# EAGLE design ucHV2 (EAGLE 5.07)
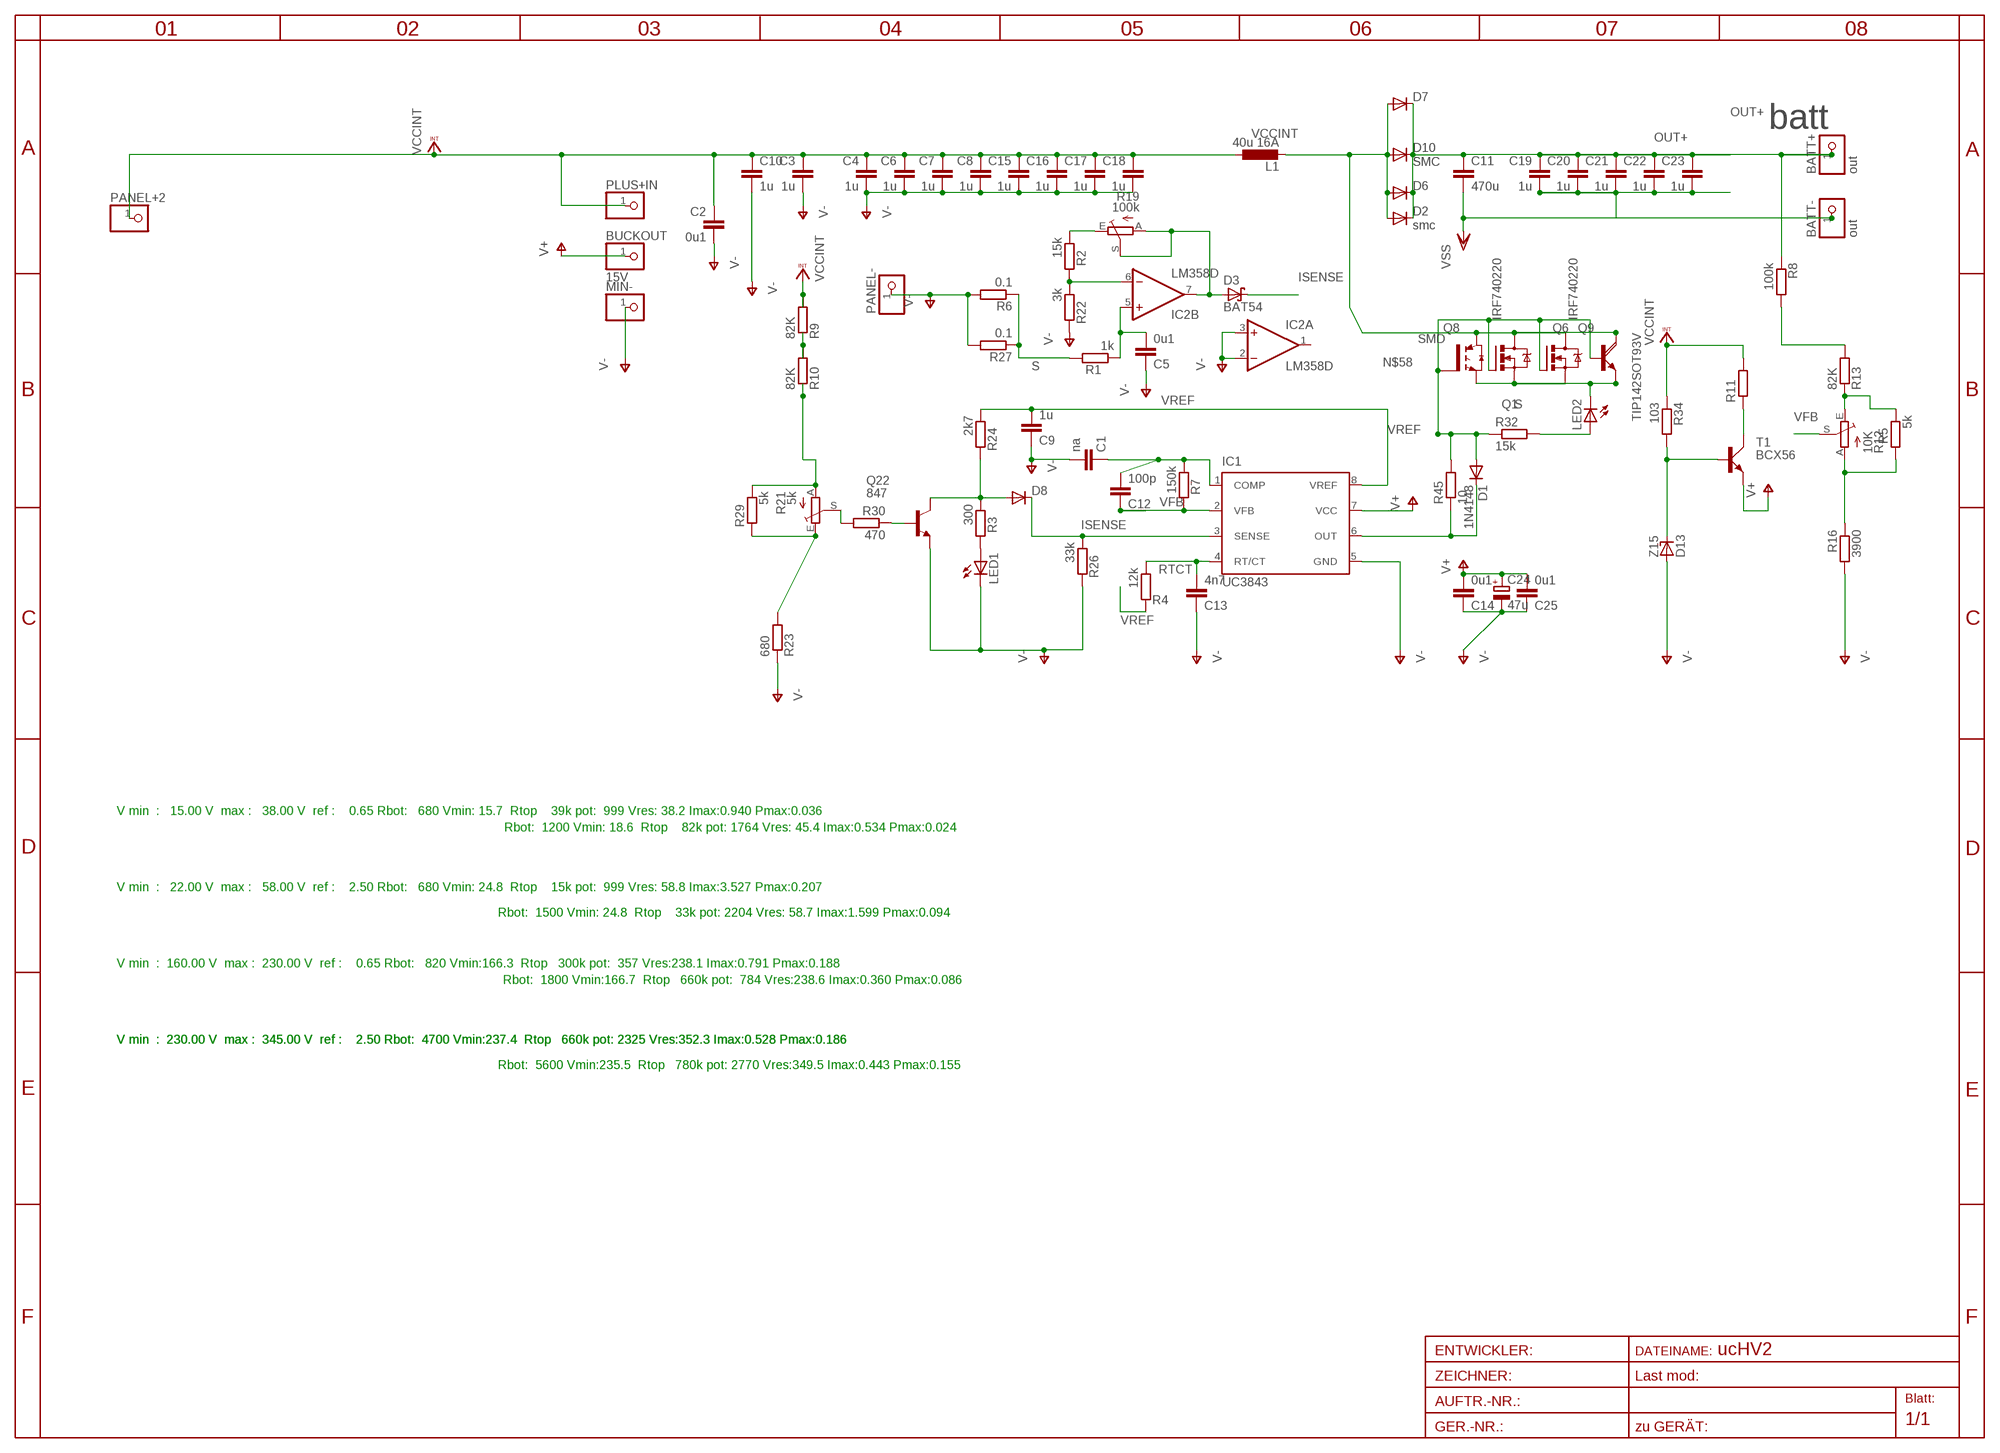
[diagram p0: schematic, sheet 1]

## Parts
BATT+  out  PINHD-1X11MM6  [1X1MM8]
BATT-  out  PINHD-1X11MM6  [1X1MM8]
BUCKOUT  15V  PINHD-1X11MM0  [1X1MM0]
C1  na  C-EUC0805  [C0805]
C2  0u1  C-EUC1206  [C1206]
C3  1u  C-EUC1206  [C1206]
C4  1u  C-EUC1206  [C1206]
C5  0u1  C-EUC0805  [C0805]
C6  1u  C-EUC1206  [C1206]
C7  1u  C-EUC1206  [C1206]
C8  1u  C-EUC1206  [C1206]
C9  1u  C-EUC1206  [C1206]
C10  1u  C-EU075-052X106  [C075-052X106]
C11  470u  C-EU075-052X106  [C075-052X106]
C12  100p  C-EUC0805  [C0805]
C13  4n7  C-EUC0805  [C0805]
C14  0u1  C-EUC3216  [C3216]
C15  1u  C-EUC1206  [C1206]
C16  1u  C-EUC1206  [C1206]
C17  1u  C-EUC1206  [C1206]
C18  1u  C-EUC1206  [C1206]
C19  1u  C-EUC1206  [C1206]
C20  1u  C-EUC1206  [C1206]
C21  1u  C-EUC1206  [C1206]
C22  1u  C-EUC1206  [C1206]
C23  1u  C-EUC1206  [C1206]
C24  47u  CPOL-EUSMCA  [SMC_A]
C25  0u1  C-EUC1206  [C1206]
D1  1N4148  DIODE-MINIMELF  [MINIMELF]
D2  smc  DIODE-SMC  [SMC]
D3  BAT54  [SOT23]
D6  DIODE-SMC  [SMC]
D7  DIODE-SMC  [SMC]
D8  DIODE-MINIMELF  [MINIMELF]
D10  SMC  DIODE-SMC  [SMC]
D13  Z15  ZENER-DIODESOD80C  [SOD80C]
IC1  UC3843  UC1843D8  [SO-08]
IC2  LM358D  [SO08]
L1  40u 16A  L-EU  [RING]
LED1  LEDCHIPLED_1206  [CHIPLED_1206]
LED2  LEDCHIPLED_1206  [CHIPLED_1206]
MIN-  PINHD-1X11MM0  [1X1MM0]
PANEL+2  PINHD-1X11MM6  [1X1MM8]
PANEL-  PINHD-1X11MM6  [1X1MM8]
PLUS+IN  PINHD-1X11MM0  [1X1MM0]
Q1  IRF740220  [TO220BV]
Q6  IRF740220  [TO220BV]
Q8  SMD  IRG4BC15UD-S  [D2PACK]
Q9  TIP142SOT93V  [SOT93V]
Q22  847  BC847ASMD  [SOT23]
R1  1k  R-EU_R0805  [R0805]
R2  15k  R-EU_R0805  [R0805]
R3  300  R-EU_R0805  [R0805]
R4  12k  R-EU_R0805  [R0805]
R5  5k  R-EU_R0805  [R0805]
R6  0.1  R-EU_0207/10  [0207/10]
R7  150k  R-EU_R0805  [R0805]
R8  100k  R-EU_R1206  [R1206]
R9  82K  R-EU_R1206  [R1206]
R10  82K  R-EU_R1206  [R1206]
R11  R-EU_0207/25  [0207/25]
R12  10K  TRIM_EU-S64W  [S64W]
R13  82K  R-EU_R1206  [R1206]
R16  3900  R-EU_R0805  [R0805]
R19  100k  TRIM_EU-S64W  [S64W]
R21  5k  TRIM_EU-S64W  [S64W]
R22  3k  R-EU_R0805  [R0805]
R23  680  R-EU_R0805  [R0805]
R24  2k7  R-EU_R0805  [R0805]
R26  33k  R-EU_R0805  [R0805]
R27  0.1  R-EU_R3216  [R3216]
R29  5k  R-EU_R1206  [R1206]
R30  470  R-EU_R0805  [R0805]
R32  15k  R-EU_R0805  [R0805]
R34  103  R-EU_R1206  [R1206]
R45  10  R-EU_R0805  [R0805]
T1  BCX56  [SOT223]

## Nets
DQ18: D2.A D6.A D7.A D10.A L1.2 Q1.D Q6.D Q8.2(C) Q9.C
ISENSE: D3.3(C) D8.C IC1.3(SENSE) R26.1
N$1: C5.2 IC2.5(B:+IN) R1.1
N$2: R2.1 R19.E
N$3: Q22.1(B) R30.1
N$4: LED1.A R3.2
N$5: LED2.A R32.2
N$6: R8.2 R13.2
N$18: C1.1 C12.2 IC1.1(COMP) R7.1
N$21: R5.2 R12.A R16.1
N$22: D3.1(A) IC2.7(B:OUT) R19.A R19.S
N$23: R11.1 T1.2(C)
N$25: D1.C IC1.6(OUT) R45.1
N$26: D13.C R34.2 T1.1(B)
N$27: IC2.6(B:-IN) R2.2 R22.1
N$30: R9.1 R10.2
N$32: R10.1 R21.A R29.1
N$34: R21.E R23.2 R29.2
N$37: R5.1 R12.E R13.1
N$58: D1.A Q1.G Q6.G Q8.1(G) Q9.B R32.1 R45.2
N$71: D8.A Q22.3(C) R3.1 R24.2
OUT+: BATT+.1 C11.1 C19.1 C20.1 C21.1 C22.1 C23.1 D2.C D6.C D7.C D10.C R8.1
PRB1: R21.S R30.2
RTCT: C13.2 IC1.4(RT/CT) R4.1
S: LED2.C Q1.S Q6.S Q8.3(E) Q9.E R1.2 R6.1 R27.1
V+: BUCKOUT.1 C14.2 C24.+ C25.2 IC1.7(VCC) T1.3(E)
V-: BATT-.1 C1.2 C2.2 C3.2 C4.2 C5.1 C6.2 C7.2 C8.2 C9.1 C10.2 C11.2 C13.1 C14.1 C15.2 C16.2 C17.2 C18.2 C19.2 C20.2 C21.2 C22.2 C23.2 C24.- C25.1 D13.A IC1.5(GND) IC2.2(A:-IN) IC2.3(A:+IN) LED1.C MIN-.1 PANEL-.1 Q22.2(E) R6.2 R16.2 R22.2 R23.1 R26.2 R27.2 ; supply symbol labelled VSS
VCCINT: C2.1 C3.1 C4.1 C6.1 C7.1 C8.1 C10.1 C15.1 C16.1 C17.1 C18.1 L1.1 PANEL+2.1 PLUS+IN.1 R9.2 R11.2 R34.1
VFB: C12.1 IC1.2(VFB) R7.2 R12.S
VREF: C9.2 IC1.8(VREF) R4.2 R24.1
Unconnected: IC2.1(A:OUT)

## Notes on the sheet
- batt
- V min  :   15.00 V  max :   38.00 V  ref :    0.65 Rbot:   680 Vmin: 15.7  Rtop    39k pot:  999 Vres: 38.2 Imax:0.940 Pmax:0.036
- Rbot:  1200 Vmin: 18.6  Rtop    82k pot: 1764 Vres: 45.4 Imax:0.534 Pmax:0.024
- V min  :   22.00 V  max :   58.00 V  ref :    2.50 Rbot:   680 Vmin: 24.8  Rtop    15k pot:  999 Vres: 58.8 Imax:3.527 Pmax:0.207
- Rbot:  1500 Vmin: 24.8  Rtop    33k pot: 2204 Vres: 58.7 Imax:1.599 Pmax:0.094
- V min  :  160.00 V  max :  230.00 V  ref :    0.65 Rbot:   820 Vmin:166.3  Rtop   300k pot:  357 Vres:238.1 Imax:0.791 Pmax:0.188
- Rbot:  1800 Vmin:166.7  Rtop   660k pot:  784 Vres:238.6 Imax:0.360 Pmax:0.086
- V min  :  230.00 V  max :  345.00 V  ref :    2.50 Rbot:  4700 Vmin:237.4  Rtop   660k pot: 2325 Vres:352.3 Imax:0.528 Pmax:0.186 | V min  :  230.00 V  max :  345.00 V  ref :    2.50 Rbot:  4700 Vmin:237.4  Rtop   660k pot: 2325 Vres:352.3 Imax:0.528 Pmax:0.186
- Rbot:  5600 Vmin:235.5  Rtop   780k pot: 2770 Vres:349.5 Imax:0.443 Pmax:0.155

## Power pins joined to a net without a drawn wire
V+: IC2.8(P:V+)
V-: IC2.4(P:V-)

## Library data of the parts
BATT+ BATT- BUCKOUT MIN- PANEL+2 PANEL- PLUS+IN = pinhead:PINHD-1X1: PIN HEADER
C1-C23 C25 = rcl:C-EU: CAPACITOR, European symbol
C24 = rcl:CPOL-EU: POLARIZED CAPACITOR, European symbol
D1 D2 D6-D8 D10 = diode:DIODE-: DIODE
D3 = diode:BAT54: Schottky Diodes
D13 = diode:ZENER-DIODE: Z-Diode
IC1 = texas:UC1843D8: PULSE WIDTH MODULATOR
IC2 = linear:LM358: OP AMP also LM158; LM258; LM2904 Source: http://cache.national.com/ds/LM/LM158.pdf
L1 = rcl:L-EU: INDUCTOR, European symbol
LED1 LED2 = led:LED: LED
Q1 Q6 = transistor-power:IRF740: N-CHANNEL MOS FET
Q8 = transistor-power:IRG4BC15UD-: INSULATED GATE BIPOLAR TRANSISTOR WITH ULTRAFAST SOFT RECOVERY DIODE
Q9 = transistor-power:TIP142: NPN DARLINGTON TRANSISTOR
Q22 = transistor-npn:BC847*: NPN Transistor
R1-R10 R13 R16 R22-R24 R26 R27 R29 R30 R34 = rcl:R-EU_: RESISTOR, European symbol
R11 R32 R45 = rcl-2:R-EU_: RESISTOR, European symbol
R12 R19 R21 = pot:TRIM_EU-: POTENTIOMETER
T1 = transistor-power:BCX56

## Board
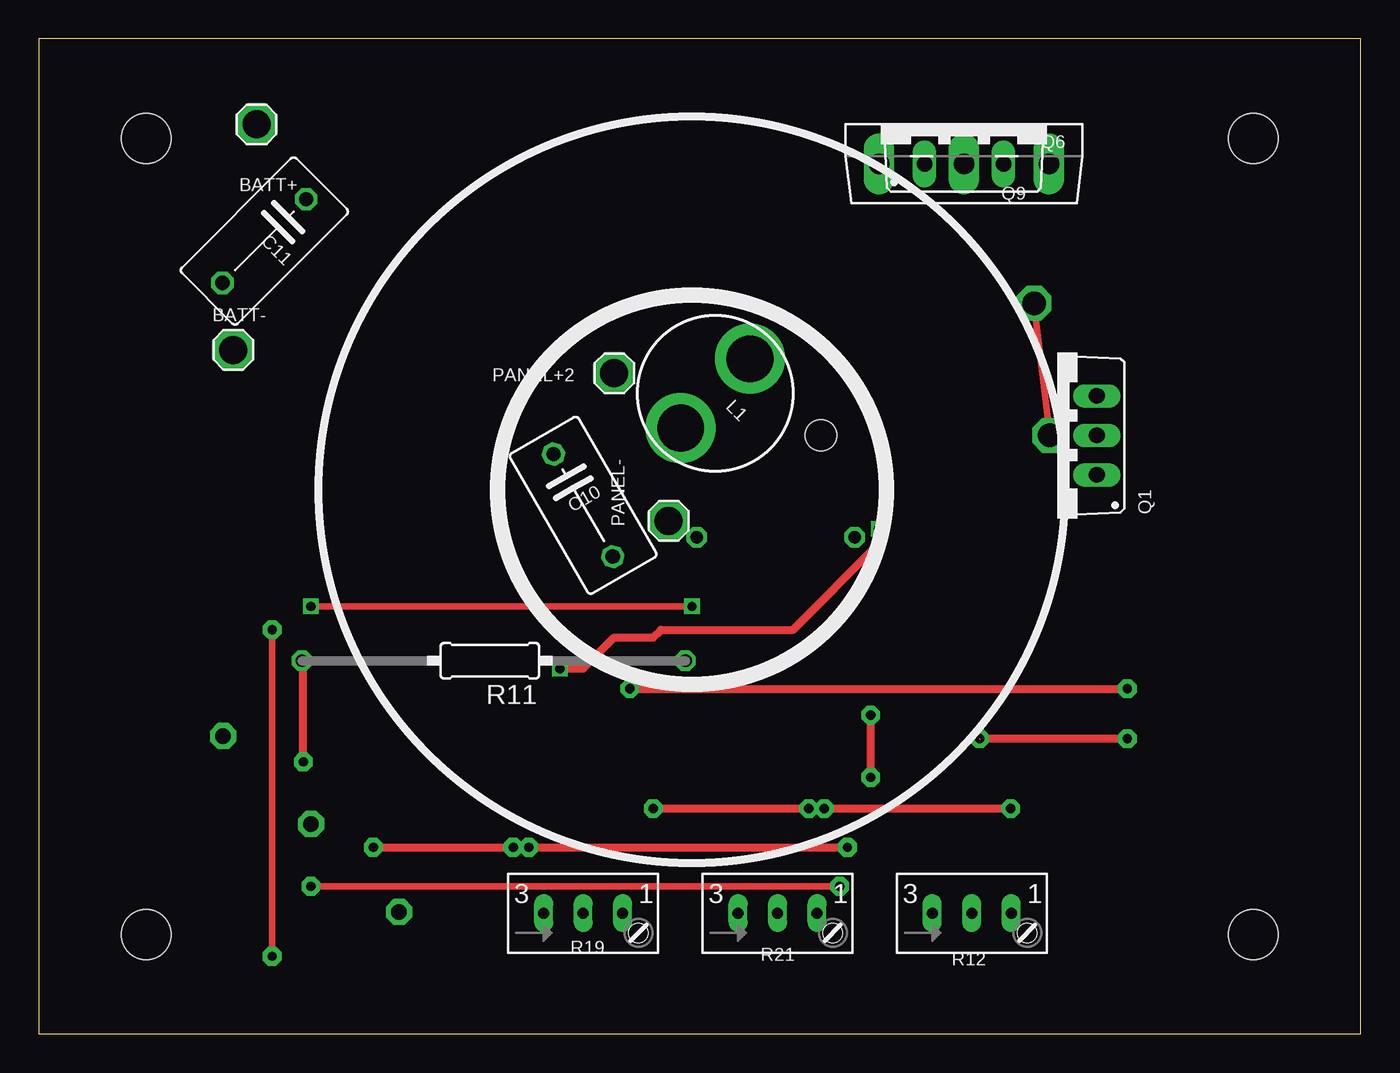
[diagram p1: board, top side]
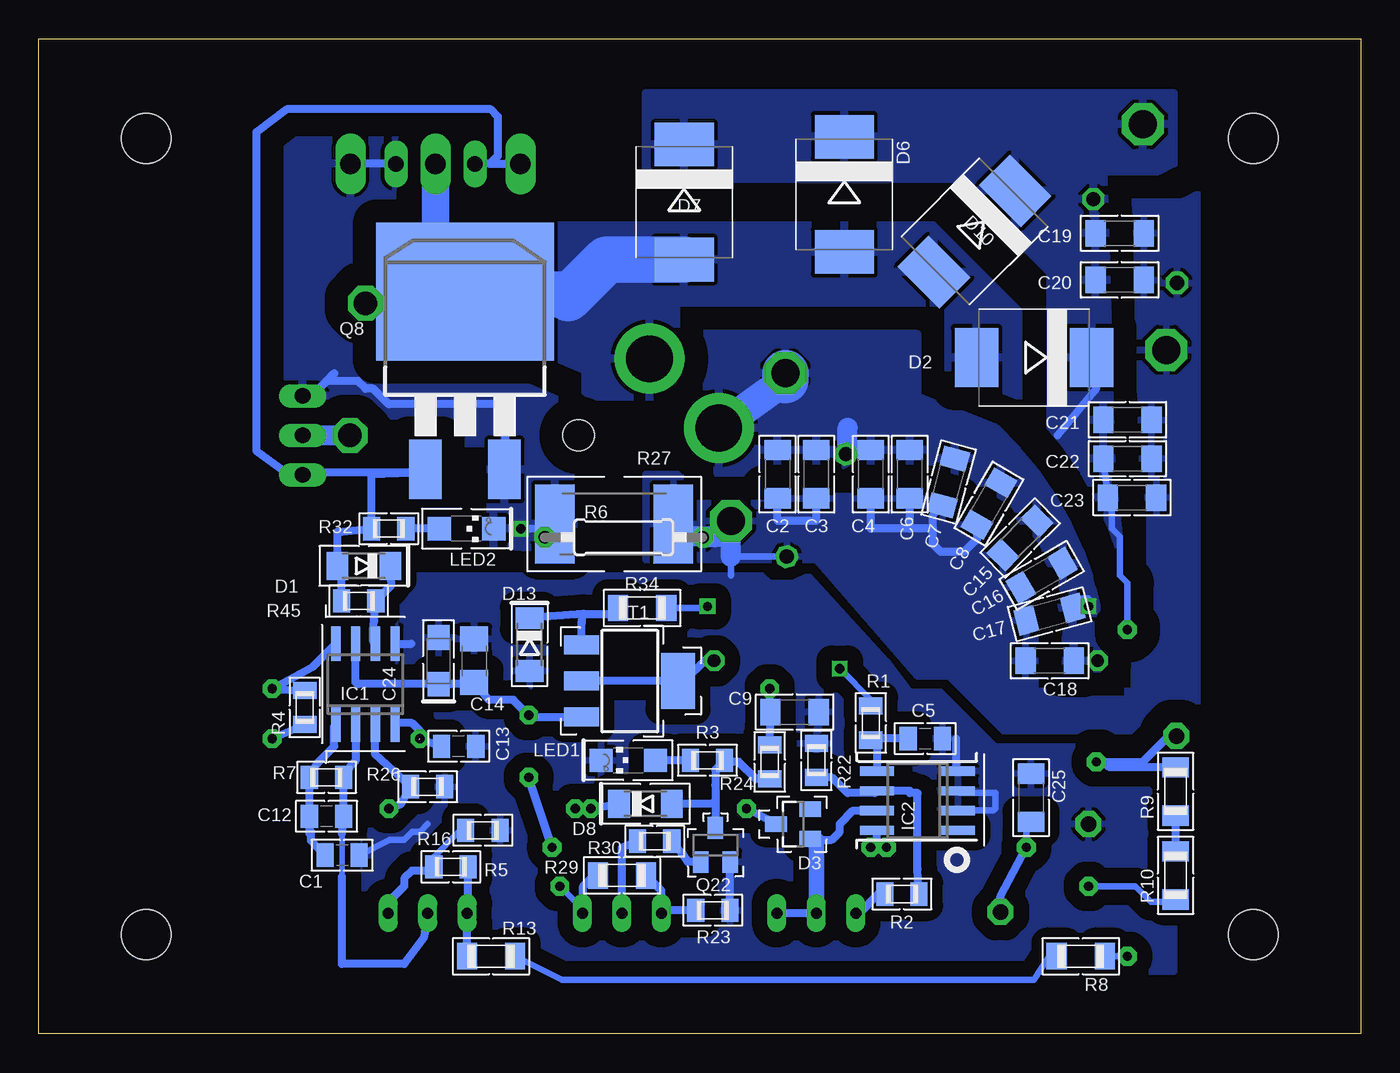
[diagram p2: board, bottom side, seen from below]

Size 85 x 64 mm. Coordinates in mm from the lower left corner, seen from the top.
Outline: 0,0 85,0 85,64 0,64 0,0
Copper layers (1*16): Top 0.035mm / dielectric 1.5mm / Bottom 0.035mm
Design rules "default *": minimum track width 10mil, minimum drill 24mil, track to track 8mil, track to pad 8mil, pad to pad 8mil, via to via 8mil, smd to smd 8mil, copper to edge 1mm, drill to drill 8mil, minimum pad ring 10mil, minimum via ring 8mil, stop-mask expansion 4mil, vias tented up to drill 0mil, thermal gap 10mil
Holes 3.2 mm at 6.9,57.6 6.9,6.4 78.1,6.4 78.1,57.6
Holes 2 mm at 50.3,38.5

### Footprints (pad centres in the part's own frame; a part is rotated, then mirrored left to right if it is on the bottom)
1X1MM8 = drill 1.8 pad 2.54 octagon: 1 0,0
1X1MM0 = drill 1 pad 1.676 octagon: 1 0,0
C0805 = smd 1.1 x 1.5: 1 -1.1,0; 2 1.1,0
C1206 = smd 1.3 x 1.7: 1 -1.55,0; 2 1.55,0
C075-052X106 = drill 0.914 octagon: 1 -3.81,0; 2 3.81,0
C3216 = smd 1.6 x 1.8: 1 -1.4,0; 2 1.4,0
SMC_A = smd 1.6 x 1.4: + -1.5,0; - 1.5,0
MINIMELF = smd 1.4 x 1.8: A 1.7,0; C -1.7,0
SMC = smd 2.8 x 3.8: A 3.7,0; C -3.7,0
SOT23 = smd 1 x 1.4: 1 -0.95,-1.1; 2 0.95,-1.1; 3 0,1.1
SOD80C = smd 1.4 x 1.8: A 1.7,0; C -1.7,0
SO-08 = smd 0.6 x 2.2: 1 -1.905,-2.6; 2 -0.635,-2.6; 3 0.635,-2.6; 4 1.905,-2.6; 5 1.905,2.6; 6 0.635,2.6; 7 -0.635,2.6; 8 -1.905,2.6
SO08 = smd 0.6 x 2.2: 1 -1.905,-2.6; 2 -0.635,-2.6; 3 0.635,-2.6; 4 1.905,-2.6; 5 1.905,2.6; 6 0.635,2.6; 7 -0.635,2.6; 8 -1.905,2.6
RING = drill 3 pad 4 round: 1 -3.15,0; 2 3.15,0
CHIPLED_1206 = smd 1.5 x 1.5: A 0,-1.75; C 0,1.75
TO220BV = drill 1.016 long: D 0,-2.54; G -2.54,-2.54; S 2.54,-2.54
D2PACK = smd 2.083 x 3.81: 1 -2.54,-8.89; 3 2.54,-8.89 | smd 11.43 x 8.89: 2 0,2.54
SOT93V = drill 1.3 pad 1.676 long: B -5.461,-2.54; C 0,-2.54; E 5.461,-2.54
R0805 = smd 1.1 x 1.5: 1 -1.1,0; 2 1.1,0
0207/10 = drill 0.813 octagon: 1 -5.08,0; 2 5.08,0
R1206 = smd 1.3 x 1.7: 1 -1.55,0; 2 1.55,0
0207/25 = drill 0.813 octagon: 1 -12.58,0; 2 12.08,0
S64W = drill 0.7 long: A 2.54,1.27; E -2.54,1.27; S 0,1.27
R3216 = smd 2.54 x 5.08: 1 -3.81,0; 2 3.81,0
SOT223 = smd 1.219 x 2.235: 1 -2.311,-3.099; 2 0,-3.099; 3 2.311,-3.099 | smd 3.6 x 2.2: 4 0,3.099

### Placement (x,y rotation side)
BATT+  14,58.5 0 top
BATT-  12.5,44 0 top
BUCKOUT  23.16,7.84 90 top
C1  65.5,11.5 0 bottom
C2  37.5,36 270 bottom
C3  35,36 270 bottom
C4  31.5,36 270 bottom
C5  28,19 180 bottom
C6  29,36 270 bottom
C7  26.5,35.5 255 bottom
C8  23.9,34.1 240 bottom
C9  36.4,20.7 180 bottom
C10  35,34 300 top
C11  14.5,51 225 top
C12  66.5,14 180 bottom
C13  58,18.5 180 bottom
C14  57,24 270 bottom
C15  21.9,31.9 225 bottom
C16  20.5,29.5 210 bottom
C17  20,27 195 bottom
C18  20,24 180 bottom
C19  15.5,51.5 0 bottom
C20  15.5,48.5 0 bottom
C21  15,39.5 0 bottom
C22  15,37 0 bottom
C23  14.7,34.5 0 bottom
C24  59.3,24 90 bottom
C25  21.2,15.2 270 bottom
D1  64.1,30.1 180 bottom
D2  21,43.5 180 bottom
D3  36.5,13.5 90 bottom
D6  33.2,54 270 bottom
D7  43.5,53.5 270 bottom
D8  46,14.8 0 bottom
D10  24.83,51.61 225 bottom
D13  53.45,25.04 270 bottom
IC1  64,22.5 0 bottom
IC2  28.5,15 90 bottom
L1  43.5,41.2 45 top
LED1  47.1,17.6 90 bottom
LED2  57.5,32.5 270 bottom
MIN-  17.5,13.5 315.7 top
PANEL+2  37,42.5 0 top
PANEL-  40.5,33 90 top
PLUS+IN  11.84,19.16 90 top
Q1  65.5,38.5 90 top
Q6  59.5,58.5 0 top
Q8  57.6,45.2 0 bottom
Q9  59.5,58.5 0 top
Q22  41.49,12.16 0 bottom
R1  31.5,20 90 bottom
R2  29.5,9 0 bottom
R3  42,17.6 180 bottom
R4  67.9,21 90 bottom
R5  58.5,10.75 180 bottom
R6  47.4,31.95 0 bottom
R7  66.5,16.5 0 bottom
R8  18,5 180 bottom
R9  11.9,15.6 90 bottom
R10  11.9,10.2 90 bottom
R11  29,24 180 top
R12  60,6.5 0 top
R13  55.92,5 0 bottom
R16  56.45,13.1 0 bottom
R19  35,6.5 0 top
R21  47.5,6.5 0 top
R22  35,17.6 90 bottom
R23  41.66,7.96 180 bottom
R24  38,17.5 270 bottom
R26  60,15.9 0 bottom
R27  48,32.8 0 bottom
R29  47.5,10.2 0 bottom
R30  45.4,12.4 180 bottom
R32  62.5,32.5 0 bottom
R34  46.2,27.4 180 bottom
R45  64.43,27.85 180 bottom
T1  47,22.7 270 bottom

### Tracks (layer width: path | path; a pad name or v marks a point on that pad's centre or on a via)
DQ18  (via drill 1.5 pad 1.2)
  Top 0.406: v64,47 v65,38.5
  Bottom 0.406: v64,47 58.9,47 58.9,47.89
  Bottom 1.27: v65,38.5 Q1.D
  Bottom 1.778: 59.5,48.04 Q9.C
  Bottom 2.54: Q8.2 58.9,47.89 59.5,48.04
  Bottom 3: Q8.2 51.04,47.54 50.97,47.34 48.51,49.8 D7.A
  pour Bottom (isolate 1.5, rank 2): 27.5,52 53,52 52,43 49.5,41 44.5,41 44.5,45.5 27.5,45.5 27.5,40.5 22,40.5 22,46.5
ISENSE  (via drill 0.6 pad 1.2)
  Top 0.5: v50.5,14.5 v62.5,14.5 | v39.5,14.5 v49.5,14.5
  Bottom 0.5: IC1.3 63.37,17.96 R26.1 61.7,14.8 v62.5,14.5 | v50.5,14.5 v49.5,14.5 D8.C | D3.3 v39.5,14.5
N$1
  Bottom 0.5: IC2.5 31.1,18.5 R1.1 31.5,19 C5.2
N$2
  Bottom 0.5: R2.1 31,9 32.23,7.77 R19.E
N$3
  Bottom 0.5: Q22.1 43.26,11.06 43.6,11.6 R30.1
N$4
  Bottom 0.5: R3.2 LED1.A
N$5
  Bottom 0.5: LED2.A R32.2
N$6
  Bottom 0.406: R8.2 20.05,4.95 21,3.5 51.37,3.5 R13.2
N$18
  Bottom 0.5: C1.1 67.5,12.45 67.5,13 67.6,12.9 C12.2 R7.1 67.1,17.4 66,18.5 66,19.8 IC1.1
N$21
  Bottom 0.406: R16.1 57.35,13 58,13 59.6,11.4 R5.2
  Bottom 0.5: R12.A 62.54,8.46 61.5,9.5 61.5,10 61,10.5 59.85,10.5 R5.2
N$22
  Bottom 0.5: IC2.7 32.63,14.37 33.5,13.5 33.5,13 34,12.5 35,12.5 35.35,12.5 D3.1 | R19.S R19.A
  Bottom 1: R19.S 35,12.5 35.4,12.5
N$23
  Bottom 0.5: T1.2 43.81,22.7 43.5,22.7 42.2,24 R11.1
N$25
  Bottom 0.5: IC1.6 63.5,25.23 63.5,26 63.43,26.57 R45.1 62.33,28.87 D1.C
N$26
  Bottom 0.5: R34.2 48.21,27 49.99,27.02 | 49.99,27.02 D13.C | T1.1 50.1,26.42 49.99,27.02
N$27
  Bottom 0.5: R2.2 28.5,10.6 28.5,15.5 29,15.5 29,15.63 IC2.6 31.23,15.5 33,15.5 34,16.5 R22.1
N$30
  Bottom 0.5: R10.2 R9.1
N$32  (via drill 0.6 pad 1.2)
  Top 0.406: v17.5,9.5 v51.5,9.5
  Bottom 0.406: R21.A 50.04,8.04 v51.5,9.5 | v17.5,9.5 14.5,9.5 13.5,8.5 12.05,8.5 R10.1
  Bottom 0.5: R29.1 49.3,10.2 50,9.5 50,7.81 R21.A
N$34
  Bottom 0.5: R23.2 44.77,7.96 R21.E 44.96,9.21 R29.2
N$37
  Bottom 0.5: R5.1 57.4,7.83 R12.E R13.1
N$58
  Bottom 0.406: Q1.G 68.5,36.46 68.5,36.11
  Bottom 0.5: 56,55.96 Q9.B | 56,55.96 Q6.G | R45.2 65.53,29.43 D1.A 65.8,32.3 R32.1 63.6,36.01 61,36.11 | 61,36.11 Q8.1 | 61,36.11 68.5,36.11 69.11,36.11 71,37.5 71,58 69,59.5 56,59.5 55.5,59 55.5,56.46 56,55.96
N$71
  Bottom 0.5: R24.2 38.9,16.4 40,17.5 40.8,17.5 R3.1 41.5,17 41.5,16 41.49,15.99 41.49,15 | 41.49,15 Q22.3 | D8.A 41.69,14.8 41.49,15
OUT+  (via drill 0.6 pad 1.2)
  Top 0.406: v15,5 v15,26
  Bottom 0.406: C22.1 C23.1 16,34.25 16,32.5 15.5,32 15.5,29.5 15,29 v15,26 | v15,5 R8.1
  Bottom 0.5: 19.5,38.5 17,41.5 17,43.7 D2.C
  pour Bottom (isolate 1.5, rank 3): 12,56 12,60.5 46,60.5 46,55 26,55 20,49 20,37.5 arc46 17,31.5 15.5,31.5 16,36.5 16.5,55.5 13,55.5
PRB1
  Bottom 0.5: R30.2 47.5,12 R21.S
RTCT  (via drill 0.6 pad 1.2)  (1 unrouted)
  Top 0.5: v60.5,19 v70,19
  Bottom 0.5: C13.2 60.55,18.95 | v70,19 R4.1 | v60.5,19 60.5,19.5 61,20 61.99,20 IC1.4
S  (via drill 0.6)
  Top 0.5: v33.5,23.5 35,23.5 37,25.5 39.5,25.5 40,26 48.5,26 54,31.5 v54,32.5
  Bottom 0.406: R1.2 31.5,21.5 v33.5,23.5
  Bottom 0.5: Q6.S Q9.E | 54.61,36.11 Q8.3 55,36.37 55,40 55.5,40.5 62.5,40.5 63.5,41.5 64,41.5 64.5,42 66.5,42 | Q1.S 66.96,41.54 66.5,42 | 66.5,42 66,42.5 | v54,32.5 53.03,32.5 R6.1
  Bottom 1.27: R6.1 51.81,31.95 R27.1
  pour Bottom (isolate 1.5): 62,58 70.5,58 71,57.5 71,39 69.5,39 68.5,40 62.5,40 60.5,38 56,38 56,31.5 50.5,31 51,40.5 54.5,42 62.5,42 63,42.5
V+  (via drill 0.6 pad 1.2)
  Top 0.5: v31.5,12 v52,12 | v53.5,16.5 v53.5,20.5 | v21.5,12 v30.5,12
  Bottom 0.406: C25.2 21.5,13.65 v21.5,12
  Bottom 0.5: IC2.8 31.1,12.1 v31.5,12 v30.5,12 | v52,12 v53.5,16.5 | IC1.7 64.64,22.64 64.5,22.5 C24.+ | C24.+ 58.5,22.5 | BUCKOUT.1 23.16,8.84 v21.5,12 | T1.3 53.39,20.39 v53.5,20.5 54.5,21.5 56.05,21.5 C14.2 57.1,22.5 C24.+
V-
  Bottom 0.406: C1.2 62.45,12.5 61.5,12.5 61,13 60.5,13 60,13.5 | C10.2 40.5,30.7 40.5,29.5 | IC2.2 23.64,14.37 23.5,14.5 23.5,15.5 25.77,15.5 IC2.3
  Bottom 0.5: IC1.5 61.05,25.1 | R23.1 40.5,8 40.5,7.5 40.54,8.47 Q22.2 | IC2.4 26,17 26,19 | C8.2 24.68,31.82 25.5,31 27,31 27.5,31.5 27.5,32.5 | 27.5,32.5 27.5,33.4 C7.2 | 29,32.5 C6.2 | 27.5,32.5 29,32.5 | C4.2 31.5,32.5 29,32.5 | C2.2 37.5,33 35,33 C3.2
  Bottom 1.27: 40.5,32 PANEL-.1 | 40.5,30.7 40.5,32 | 40.5,32 41,32 | 41,32 44.19,32 R27.2 | R6.2 41.5,31.95 41,32
  pour Bottom (isolate 1.5, rank 4): 28.5,23 26.5,23 23,19.5 12.5,19.5 10.5,21 10.5,54.5 17,54.5 16.5,23.5 20,23.5 arc-61 26.5,36 46,36 46,30.5 35,30.5
  pour Bottom (isolate 1): 35.5,29.5 36.5,29 38,29 38.5,29.5 70,29.5 70,4 12,4 12,18.5 23.5,18.5 27,22 29,22 30.5,24
VCCINT  (via drill 0.6, 0.6 pad 1.2)
  Top 0.406: v17.5,27.5 v42,27.5
  Top 0.5: v17,17.5 v17,24
  Bottom 0.406: 17.5,28 17.9,28 C17.1 18.5,27.5 v17.5,27.5 | R34.1 42,27.4 v42,27.5
  Bottom 0.5: PLUS+IN.1 12.34,19.16 14,17.5 16.5,17.5 | 16.5,17.5 v17,17.5 | R9.2 16.15,17.15 16.5,17.5
  Bottom 1.27: C10.1 33,37.3 33,39
  Bottom 2: 37,42.05 L1.1
  Bottom 3: PANEL+2.1 37,42.05
  pour Bottom (isolate 1.5): 28.5,45 42.5,45 42.5,36 27.5,35.5 arc83 19,23.5 16.5,23.5 arc-46 23.5,39 28.5,41
VFB
  Bottom 0.35: 65.5,10.13 65.5,12.9
  Bottom 0.5: R12.S 60.2,6.29 61.5,4.5 65.5,4.5 65.5,10.13 | 65.5,12.9 65.4,13.66 C12.1 R7.2 64.9,17.3 64.6,17.6 64.6,19.86 IC1.2
VREF  (via drill 0.6 pad 1.2)
  Top 0.5: v38,22.2 v70,22.2
  Bottom 0.5: R24.1 C9.2 38,21.95 v38,22.2 | IC1.8 67.41,23.59 v70,22.2 68.4,22.1 R4.2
